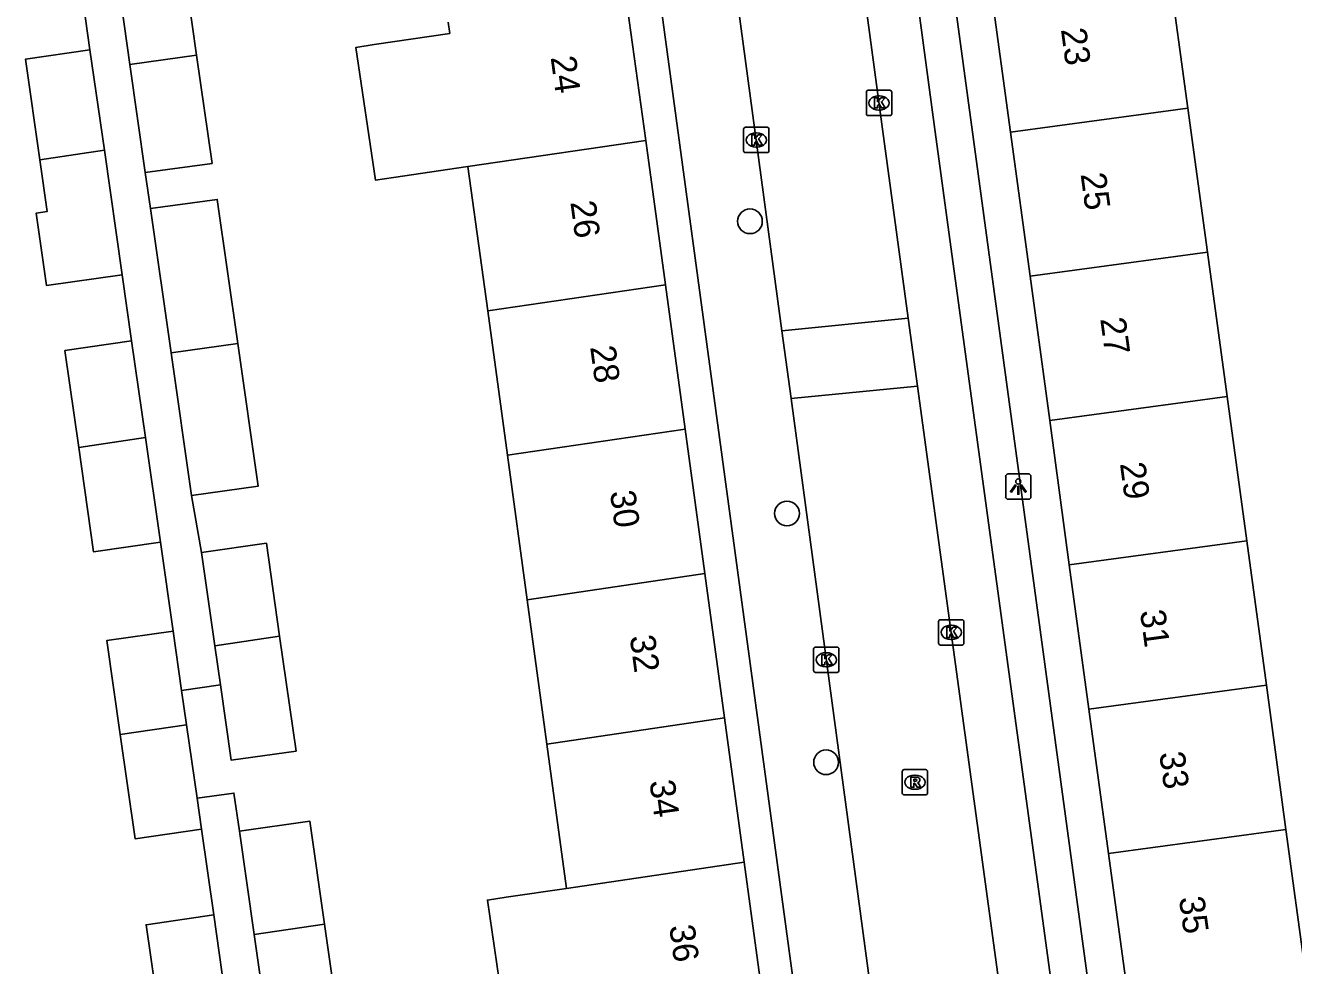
# Model space of a CAD drawing. Extents: x 159053 to 160041, y 380450 to 381422.
# Drawn here: x 159648.2 to 159698.4, y 381063.5 to 381100.6 of the extents above; entities that cross this region are included whole.
import ezdxf

# ---------------------------------------------------------------- set-up
doc = ezdxf.new("R2010")
doc.units = 0
for name, color, linetype in [('IMGEO_Boom', 7, 'Continuous'), ('IMGEO_Kolk', 7, 'Continuous'), ('IMGEO_Lichtpunt', 7, 'Continuous'), ('IMGEO_Pand', 7, 'Continuous'), ('IMGEO_Pand_nummerreeks', 7, 'Continuous'), ('IMGEO_Rijbaan_lokaal_open', 7, 'Continuous'), ('IMGEO_Rioolput', 7, 'Continuous'), ('IMGEO_Voetpad_open', 7, 'Continuous')]:
    doc.layers.add(name, color=color, linetype=linetype)

msp = doc.modelspace()

# ---------------------------------------------------------------- linework, layer by layer
at = {"layer": 'IMGEO_Boom'}
for centre in [(159676.866, 381092.89), (159678.33, 381081.344), (159679.876, 381071.512)]:
    msp.add_circle(centre, 0.489, dxfattribs=at)
at = {"layer": 'IMGEO_Kolk'}
for p, q in [((159681.467, 381097.141), (159681.467, 381097.993)), ((159681.542, 381098.067), (159682.394, 381098.067)), ((159681.955, 381097.847), (159681.98, 381097.847)), ((159682.468, 381097.993), (159682.468, 381097.141)), ((159682.394, 381097.067), (159681.542, 381097.067)), ((159681.978, 381097.287), (159681.953, 381097.287)), ((159676.615, 381095.677), (159676.615, 381096.529)), ((159676.69, 381096.603), (159677.542, 381096.603)), ((159677.103, 381096.383), (159677.128, 381096.383)), ((159677.616, 381096.529), (159677.616, 381095.677)), ((159677.126, 381095.823), (159677.101, 381095.823)), ((159677.542, 381095.603), (159676.69, 381095.603)), ((159684.32, 381076.219), (159684.32, 381077.071)), ((159684.395, 381077.145), (159685.247, 381077.145)), ((159684.808, 381076.925), (159684.833, 381076.925)), ((159685.321, 381077.071), (159685.321, 381076.219)), ((159684.831, 381076.365), (159684.806, 381076.365)), ((159679.381, 381075.135), (159679.381, 381075.987)), ((159679.456, 381076.061), (159680.308, 381076.061)), ((159679.869, 381075.841), (159679.894, 381075.841)), ((159680.382, 381075.987), (159680.382, 381075.135)), ((159685.247, 381076.145), (159684.395, 381076.145)), ((159679.892, 381075.281), (159679.867, 381075.281)), ((159680.308, 381075.061), (159679.456, 381075.061))]:
    msp.add_line(p, q, dxfattribs=at)
for points in [[(159681.467, 381097.141), (159681.467, 381097.993)], [(159681.542, 381098.067), (159682.394, 381098.067)], [(159682.468, 381097.993), (159682.468, 381097.141)], [(159681.788, 381097.767), (159681.911, 381097.767), (159681.911, 381097.616), (159682.041, 381097.767), (159682.205, 381097.767), (159682.059, 381097.616), (159682.212, 381097.367), (159682.06, 381097.367), (159681.975, 381097.531), (159681.911, 381097.464), (159681.911, 381097.367), (159681.788, 381097.367), (159681.788, 381097.767)], [(159682.394, 381097.067), (159681.542, 381097.067)], [(159676.615, 381095.677), (159676.615, 381096.529)], [(159676.69, 381096.603), (159677.542, 381096.603)], [(159677.616, 381096.529), (159677.616, 381095.677)], [(159676.936, 381096.303), (159677.059, 381096.303), (159677.059, 381096.152), (159677.189, 381096.303), (159677.353, 381096.303), (159677.207, 381096.152), (159677.36, 381095.903), (159677.208, 381095.903), (159677.123, 381096.067), (159677.059, 381096), (159677.059, 381095.903), (159676.936, 381095.903), (159676.936, 381096.303)], [(159677.542, 381095.603), (159676.69, 381095.603)], [(159684.32, 381076.219), (159684.32, 381077.071)], [(159684.395, 381077.145), (159685.247, 381077.145)], [(159684.641, 381076.845), (159684.764, 381076.845), (159684.764, 381076.694), (159684.894, 381076.845), (159685.058, 381076.845), (159684.912, 381076.694), (159685.065, 381076.445), (159684.913, 381076.445), (159684.828, 381076.609), (159684.764, 381076.542), (159684.764, 381076.445), (159684.641, 381076.445), (159684.641, 381076.845)], [(159685.321, 381077.071), (159685.321, 381076.219)], [(159679.381, 381075.135), (159679.381, 381075.987)], [(159679.456, 381076.061), (159680.308, 381076.061)], [(159680.382, 381075.987), (159680.382, 381075.135)], [(159685.247, 381076.145), (159684.395, 381076.145)], [(159679.702, 381075.761), (159679.825, 381075.761), (159679.825, 381075.61), (159679.955, 381075.761), (159680.119, 381075.761), (159679.973, 381075.61), (159680.126, 381075.361), (159679.974, 381075.361), (159679.889, 381075.525), (159679.825, 381075.458), (159679.825, 381075.361), (159679.702, 381075.361), (159679.702, 381075.761)], [(159680.308, 381075.061), (159679.456, 381075.061)]]:
    msp.add_lwpolyline(points, dxfattribs=at)
for centre, start, end in [((159681.544, 381097.991), 91.552, 178.448), ((159681.544, 381097.991), 91.552, 178.448), ((159682.392, 381097.991), 1.552, 88.448), ((159682.392, 381097.991), 1.552, 88.448), ((159681.544, 381097.143), 181.552, 268.448), ((159681.544, 381097.143), 181.552, 268.448), ((159682.392, 381097.143), 271.552, 358.448), ((159682.392, 381097.143), 271.552, 358.448), ((159676.692, 381096.527), 91.552, 178.448), ((159676.692, 381096.527), 91.552, 178.448), ((159677.54, 381096.527), 1.552, 88.448), ((159677.54, 381096.527), 1.552, 88.448), ((159676.692, 381095.679), 181.552, 268.448), ((159676.692, 381095.679), 181.552, 268.448), ((159677.54, 381095.679), 271.552, 358.448), ((159677.54, 381095.679), 271.552, 358.448), ((159684.397, 381077.069), 91.552, 178.448), ((159684.397, 381077.069), 91.552, 178.448), ((159685.245, 381077.069), 1.552, 88.448), ((159685.245, 381077.069), 1.552, 88.448), ((159679.458, 381075.985), 91.552, 178.448), ((159679.458, 381075.985), 91.552, 178.448), ((159680.306, 381075.985), 1.552, 88.448), ((159680.306, 381075.985), 1.552, 88.448), ((159684.397, 381076.221), 181.552, 268.448), ((159684.397, 381076.221), 181.552, 268.448), ((159685.245, 381076.221), 271.552, 358.448), ((159685.245, 381076.221), 271.552, 358.448), ((159679.458, 381075.137), 181.552, 268.448), ((159679.458, 381075.137), 181.552, 268.448), ((159680.306, 381075.137), 271.552, 358.448), ((159680.306, 381075.137), 271.552, 358.448)]:
    msp.add_arc(centre, 0.0765, start, end, dxfattribs=at)
for centre, major_axis, ratio, start_param, end_param in [((159681.954, 381097.567), (-0.387, 0.002), 0.722429, 4.712389, 7.853982), ((159681.979, 381097.567), (-0.39, 0.002), 0.717154, 1.570796, 4.712389), ((159677.102, 381096.103), (-0.387, 0.002), 0.722429, 4.712389, 7.853982), ((159677.127, 381096.103), (-0.39, 0.002), 0.717154, 1.570796, 4.712389), ((159684.807, 381076.645), (-0.387, 0.002), 0.722429, 4.712389, 7.853982), ((159684.832, 381076.645), (-0.39, 0.002), 0.717154, 1.570796, 4.712389), ((159679.868, 381075.561), (-0.387, 0.002), 0.722429, 4.712389, 7.853982), ((159679.893, 381075.561), (-0.39, 0.002), 0.717154, 1.570796, 4.712389)]:
    msp.add_ellipse(centre, major_axis=major_axis, ratio=ratio, start_param=start_param, end_param=end_param, dxfattribs=at)
at = {"layer": 'IMGEO_Lichtpunt'}
for p, q in [((159686.973, 381082.809), (159686.973, 381082.002)), ((159686.973, 381082.809), (159686.973, 381082.002)), ((159687.875, 381082.904), (159687.067, 381082.904)), ((159687.875, 381082.904), (159687.067, 381082.904)), ((159687.969, 381082.002), (159687.969, 381082.809)), ((159687.969, 381082.002), (159687.969, 381082.809)), ((159687.067, 381081.908), (159687.875, 381081.908)), ((159687.067, 381081.908), (159687.875, 381081.908))]:
    msp.add_line(p, q, dxfattribs=at)
for points in [[(159687.347, 381082.473), (159687.386, 381082.445), (159687.198, 381082.183), (159687.16, 381082.21), (159687.347, 381082.473)], [(159687.449, 381082.425), (159687.496, 381082.425), (159687.496, 381082.103), (159687.449, 381082.103), (159687.449, 381082.425)], [(159687.559, 381082.445), (159687.597, 381082.472), (159687.784, 381082.21), (159687.745, 381082.182), (159687.559, 381082.445)]]:
    msp.add_lwpolyline(points, dxfattribs=at)
msp.add_circle((159687.472, 381082.607), 0.0994, dxfattribs=at)
for centre, start, end in [((159687.067, 381082.809), 90, 180), ((159687.067, 381082.809), 90, 180), ((159687.875, 381082.809), 0, 90), ((159687.875, 381082.809), 0, 90), ((159687.067, 381082.002), 180, 270), ((159687.067, 381082.002), 180, 270), ((159687.875, 381082.002), 270, 0), ((159687.875, 381082.002), 270, 360)]:
    msp.add_arc(centre, 0.0946, start, end, dxfattribs=at)
at = {"layer": 'IMGEO_Pand'}
for points in [[(159693.4, 381103.068), (159694.176, 381097.366)], [(159654.994, 381099.452), (159654.645, 381101.896), (159652.007, 381101.519)], [(159687.162, 381096.417), (159686.387, 381102.118)], [(159652.007, 381101.519), (159652.354, 381099.091)], [(159671.965, 381101.792), (159672.744, 381096.087)], [(159665.721, 381095.053), (159662.78, 381094.62), (159662.065, 381094.515), (159661.292, 381099.764), (159662.007, 381099.87), (159665.003, 381100.311), (159664.942, 381100.757)], [(159648.795, 381095.322), (159648.227, 381099.293), (159650.781, 381099.666)], [(159650.781, 381099.666), (159651.349, 381095.696)], [(159654.994, 381099.452), (159652.354, 381099.091)], [(159652.966, 381094.816), (159655.606, 381095.177), (159654.994, 381099.452)], [(159652.354, 381099.091), (159652.966, 381094.816)], [(159694.176, 381097.366), (159687.162, 381096.417)], [(159694.176, 381097.366), (159694.951, 381091.665)], [(159687.937, 381090.715), (159687.162, 381096.417)], [(159665.721, 381095.053), (159672.744, 381096.087)], [(159672.744, 381096.087), (159673.523, 381090.382)], [(159648.795, 381095.322), (159649.087, 381093.272), (159648.658, 381093.211), (159649.067, 381090.348), (159652.053, 381090.775)], [(159651.349, 381095.696), (159648.795, 381095.322)], [(159652.053, 381090.775), (159651.349, 381095.696)], [(159666.5, 381089.347), (159665.721, 381095.053)], [(159656.624, 381088.059), (159655.809, 381093.756), (159653.169, 381093.395)], [(159653.169, 381093.395), (159653.984, 381087.698)], [(159687.937, 381090.715), (159694.951, 381091.665)], [(159694.951, 381091.665), (159695.726, 381085.963)], [(159666.5, 381089.347), (159673.523, 381090.382)], [(159673.523, 381090.382), (159674.302, 381084.676)], [(159688.712, 381085.013), (159687.937, 381090.715)], [(159667.279, 381083.642), (159666.5, 381089.347)], [(159652.427, 381088.161), (159649.787, 381087.783), (159650.334, 381083.957)], [(159652.973, 381084.344), (159652.427, 381088.161)], [(159656.624, 381088.059), (159653.984, 381087.698)], [(159654.792, 381082.052), (159657.429, 381082.429), (159656.624, 381088.059)], [(159653.984, 381087.698), (159654.792, 381082.052)], [(159695.726, 381085.963), (159688.712, 381085.013)], [(159695.726, 381085.963), (159696.501, 381080.262)], [(159689.487, 381079.312), (159688.712, 381085.013)], [(159652.973, 381084.344), (159650.334, 381083.957)], [(159653.566, 381080.205), (159652.973, 381084.344)], [(159674.302, 381084.676), (159667.279, 381083.642)], [(159674.302, 381084.676), (159675.081, 381078.971)], [(159650.334, 381083.957), (159650.924, 381079.827), (159653.566, 381080.205)], [(159668.058, 381077.936), (159667.279, 381083.642)], [(159658.278, 381076.494), (159657.753, 381080.168), (159655.188, 381079.801)], [(159655.188, 381079.801), (159655.716, 381076.116)], [(159696.501, 381080.262), (159689.487, 381079.312)], [(159696.501, 381080.262), (159697.276, 381074.56)], [(159690.262, 381073.61), (159689.487, 381079.312)], [(159668.058, 381077.936), (159675.081, 381078.971)], [(159675.081, 381078.971), (159675.86, 381073.265)], [(159668.837, 381072.231), (159668.058, 381077.936)], [(159654.068, 381076.694), (159651.445, 381076.319), (159651.977, 381072.607)], [(159654.404, 381074.349), (159654.068, 381076.694)], [(159658.278, 381076.494), (159655.716, 381076.116)], [(159655.938, 381074.566), (159656.363, 381071.591), (159658.927, 381071.957), (159658.278, 381076.494)], [(159655.716, 381076.116), (159655.938, 381074.566)], [(159654.598, 381072.992), (159654.404, 381074.349)], [(159690.262, 381073.61), (159697.276, 381074.56)], [(159697.276, 381074.56), (159698.051, 381068.859)], [(159691.037, 381067.91), (159690.262, 381073.61)], [(159651.977, 381072.607), (159654.598, 381072.992)], [(159655.014, 381070.088), (159654.598, 381072.992)], [(159668.837, 381072.231), (159675.86, 381073.265)], [(159675.86, 381073.265), (159676.639, 381067.56)], [(159651.977, 381072.607), (159652.567, 381068.486), (159655.188, 381068.871)], [(159669.616, 381066.526), (159668.837, 381072.231)], [(159655.188, 381068.871), (159655.014, 381070.088)], [(159656.689, 381068.788), (159659.466, 381069.185), (159660.048, 381065.116)], [(159657.273, 381064.707), (159656.689, 381068.788)], [(159698.051, 381068.859), (159691.037, 381067.91)], [(159698.051, 381068.859), (159698.826, 381063.158)], [(159691.812, 381062.208), (159691.037, 381067.91)], [(159676.639, 381067.56), (159669.616, 381066.526)], [(159676.639, 381067.56), (159677.418, 381061.855)], [(159670.395, 381060.82), (159668.069, 381060.478), (159667.324, 381060.369), (159666.486, 381066.065), (159667.23, 381066.175), (159669.616, 381066.526)], [(159655.672, 381065.485), (159652.999, 381065.093), (159653.549, 381061.248)], [(159656.222, 381061.64), (159655.672, 381065.485)], [(159660.048, 381065.116), (159657.273, 381064.707)], [(159657.853, 381060.658), (159660.63, 381061.055), (159660.048, 381065.116)], [(159657.273, 381064.707), (159657.853, 381060.658)]]:
    msp.add_lwpolyline(points, dxfattribs=at)
at = {"layer": 'IMGEO_Rijbaan_lokaal_open'}
for points in [[(159679.778, 381113.869), (159682.144, 381096.247), (159683.125, 381089.062)], [(159678.132, 381088.567), (159674.799, 381113.326)], [(159678.132, 381088.567), (159683.125, 381089.062)], [(159683.125, 381089.062), (159683.492, 381086.37)], [(159678.493, 381085.883), (159678.132, 381088.567)], [(159683.492, 381086.37), (159678.493, 381085.883)], [(159683.492, 381086.37), (159688.653, 381048.555), (159689.604, 381041.734), (159691.441, 381027.917)], [(159689.262, 381006.55), (159688.989, 381008.512), (159687.185, 381021.364), (159686.517, 381026.277), (159678.493, 381085.883)]]:
    msp.add_lwpolyline(points, dxfattribs=at)
at = {"layer": 'IMGEO_Rioolput'}
for p, q in [((159682.883, 381070.297), (159682.883, 381071.149)), ((159682.958, 381071.223), (159683.81, 381071.223)), ((159683.371, 381071.003), (159683.396, 381071.003)), ((159683.884, 381071.149), (159683.884, 381070.297)), ((159683.394, 381070.443), (159683.369, 381070.443)), ((159683.81, 381070.223), (159682.958, 381070.223))]:
    msp.add_line(p, q, dxfattribs=at)
for points in [[(159682.883, 381070.297), (159682.883, 381071.149)], [(159682.958, 381071.223), (159683.81, 381071.223)], [(159683.472, 381070.921), (159683.22, 381070.923), (159683.22, 381070.523)], [(159683.398, 381070.842), (159683.344, 381070.842), (159683.344, 381070.761)], [(159683.344, 381070.761), (159683.396, 381070.761)], [(159683.884, 381071.149), (159683.884, 381070.297)], [(159683.22, 381070.523), (159683.344, 381070.523), (159683.344, 381070.685), (159683.355, 381070.685)], [(159683.402, 381070.656), (159683.473, 381070.523), (159683.613, 381070.523), (159683.548, 381070.649)], [(159683.81, 381070.223), (159682.958, 381070.223)]]:
    msp.add_lwpolyline(points, dxfattribs=at)
for centre, radius, start, end in [((159682.96, 381071.147), 0.0765, 91.552, 178.448), ((159682.96, 381071.147), 0.0765, 91.552, 178.448), ((159683.38, 381070.95), 0.19, 274.7715, 282.9687), ((159683.404, 381070.746), 0.0964, 77.0061, 93.1865), ((159683.418, 381070.803), 0.0378, 276.6634, 79.6772), ((159683.471, 381070.811), 0.109, 350.3612, 89.416), ((159683.469, 381070.811), 0.112, 277.5842, 350.9817), ((159683.808, 381071.147), 0.0765, 1.552, 88.448), ((159683.808, 381071.147), 0.0765, 1.552, 88.448), ((159682.96, 381070.299), 0.0765, 181.552, 268.448), ((159682.96, 381070.299), 0.0765, 181.552, 268.448), ((159683.354, 381070.632), 0.0533, 26.0293, 88.6989), ((159683.453, 381070.596), 0.108, 29.5134, 73.7905), ((159683.808, 381070.299), 0.0765, 271.552, 358.448), ((159683.808, 381070.299), 0.0765, 271.552, 358.448)]:
    msp.add_arc(centre, radius, start, end, dxfattribs=at)
for centre, major_axis, ratio, start_param, end_param in [((159683.37, 381070.723), (-0.387, 0.002), 0.722429, 4.712389, 7.853982), ((159683.395, 381070.723), (-0.39, 0.002), 0.717154, 1.570796, 4.712389)]:
    msp.add_ellipse(centre, major_axis=major_axis, ratio=ratio, start_param=start_param, end_param=end_param, dxfattribs=at)
at = {"layer": 'IMGEO_Voetpad_open'}
for points in [[(159668.05, 381130.466), (159669.393, 381130.571), (159683.353, 381027.651)], [(159681.977, 381130.689), (159681.022, 381130.534), (159695.018, 381027.623)], [(159679.729, 381129.583), (159684.168, 381096.521), (159690.677, 381048.834), (159693.064, 381031.721)], [(159650.322, 381102.873), (159650.781, 381099.666)], [(159653.169, 381093.395), (159652.966, 381094.816)], [(159652.053, 381090.775), (159652.427, 381088.161)], [(159655.188, 381079.801), (159654.792, 381082.052)], [(159653.566, 381080.205), (159654.068, 381076.694)], [(159654.404, 381074.349), (159655.938, 381074.566)], [(159655.014, 381070.088), (159656.473, 381070.295), (159656.689, 381068.788)], [(159655.188, 381068.871), (159655.672, 381065.485)]]:
    msp.add_lwpolyline(points, dxfattribs=at)

# ---------------------------------------------------------------- texts
at = {"layer": 'IMGEO_Pand_nummerreeks'}
for s, rotation, p in [('23', 277.7419, (159689.154, 381100.474)), ('24', 277.7748, (159668.986, 381099.369)), ('25', 277.7419, (159689.932, 381094.754)), ('26', 277.775, (159669.766, 381093.647)), ('27', 277.7419, (159690.709, 381089.035)), ('28', 277.775, (159670.548, 381087.922)), ('29', 277.7419, (159691.487, 381083.315)), ('30', 277.775, (159671.33, 381082.2)), ('31', 277.7419, (159692.279, 381077.484)), ('32', 277.775, (159672.11, 381076.484)), ('33', 277.7419, (159693.042, 381071.876)), ('34', 277.775, (159672.891, 381070.759)), ('35', 277.7419, (159693.819, 381066.157)), ('36', 277.7748, (159673.673, 381065.037))]:
    msp.add_text(s, height=1, rotation=rotation, dxfattribs=at).set_placement(p)

doc.saveas('drawing.dxf')
